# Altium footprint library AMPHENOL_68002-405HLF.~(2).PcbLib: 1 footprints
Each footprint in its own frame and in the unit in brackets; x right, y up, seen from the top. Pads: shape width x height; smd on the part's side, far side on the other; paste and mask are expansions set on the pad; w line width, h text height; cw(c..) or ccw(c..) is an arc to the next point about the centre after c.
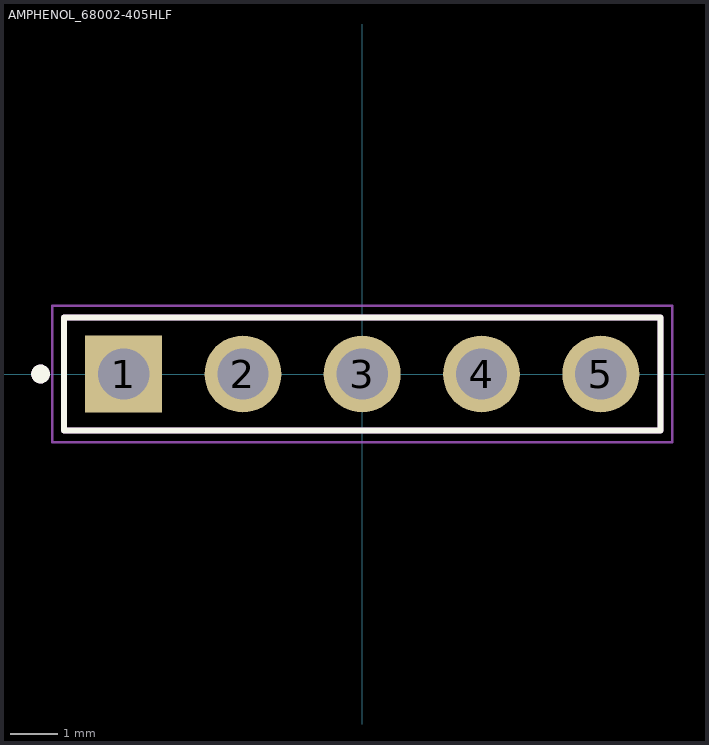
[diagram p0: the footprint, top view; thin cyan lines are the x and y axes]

## AMPHENOL_68002-405HLF [mil] "5 Pin 5Pos THT BergeStick 2.54MM Amphenol68002-405HLF 3A"
height 337.8
pads (5):
  rect 64.5x64.5 / inner round 64.5 / far side rect 64.5x64.5 hole 43: 1(-200,0)
  round 64.5 hole 43: 2(-100,0) 3(0,0) 4(100,0) 5(200,0)
Top Overlay:
  circle w7.87: c-269.69,0 r3.94
  lines w5: -250,-47.5 -250,47.5 250,47.5 250,-47.5 -250,-47.5
Assembly Top:
  circle w7.87: c-269.69,0 r3.94
  lines w5: -250,-47.5 -250,47.5 250,47.5 250,-47.5 -250,-47.5
Courtyard Top:
  lines w1.97: -259.84,-57.34 259.84,-57.34 259.84,57.34 -259.84,57.34 -259.84,-57.34
3D body "step_temp.STEP": height 329.92, standoff -150, extent -250,-47.44 250,47.44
